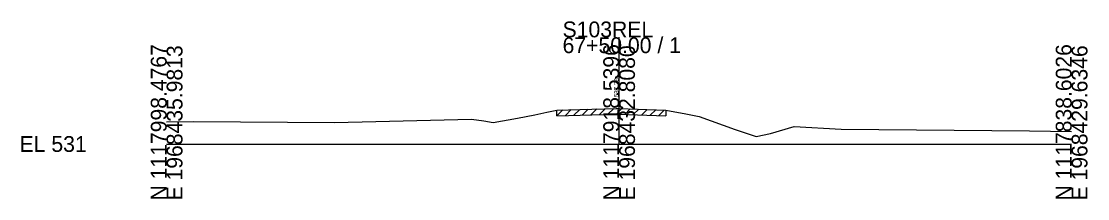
# Model space of a CAD drawing. Extents: x -26 to 163, y -10 to 24518.
# Drawn here: x -25.7 to 162.8, y 15990.3 to 16021.7 of the extents above; entities that cross this region are included whole.
import ezdxf

# ---------------------------------------------------------------- set-up
doc = ezdxf.new("R2010")
doc.units = 0
for name, color, linetype in [('RD_GPK_XS_Cell', 7, 'Continuous'), ('RD_XS_ExGround', 7, 'Continuous'), ('RD_XS_ExPaveRet', 7, 'Continuous'), ('RD_XS_TX_Elev_EX', 7, 'Continuous')]:
    doc.layers.add(name, color=color, linetype=linetype)

msp = doc.modelspace()

# ---------------------------------------------------------------- linework, layer by layer
at = {"layer": 'RD_GPK_XS_Cell'}
for p, q in [((80, 16000), (80, 16018.9)), ((0, 16000), (80, 16000)), ((80, 16000), (160, 16000))]:
    msp.add_line(p, q, dxfattribs=at)
at = {"layer": 'RD_XS_ExGround'}
msp.add_lwpolyline([(0, 16003.91), (4.73, 16003.97), (29.7, 16003.81), (37.01, 16003.98), (53.91, 16004.39), (56.1, 16004.09), (57.73, 16003.8), (62.05, 16004.58), (65.07, 16005.14), (67.24, 16005.65), (69.01, 16006.01), (75.15, 16006.19), (79.45, 16006.3), (80, 16006.28), (83.26, 16006.18), (88.24, 16006.02), (91.79, 16005.33), (94.17, 16004.89), (100.49, 16002.56), (104.2, 16001.32), (106.76, 16001.87), (110.97, 16003.08), (119.27, 16002.63), (152.57, 16002.35), (160, 16002.22)], dxfattribs=at)
at = {"layer": 'RD_XS_ExPaveRet'}
for p, q in [((69.01, 16005.01), (70.04, 16006.04)), ((69.01, 16005.01), (69.01, 16006.01)), ((69.01, 16005.01), (75.15, 16005.19)), ((70.51, 16005.06), (71.54, 16006.09)), ((72.01, 16005.1), (73.04, 16006.13)), ((73.51, 16005.14), (74.54, 16006.17)), ((75.01, 16005.18), (76.04, 16006.21)), ((75.15, 16005.19), (79.45, 16005.3)), ((76.51, 16005.22), (77.54, 16006.25)), ((78.01, 16005.26), (79.04, 16006.29)), ((79.45, 16005.3), (80, 16005.28)), ((79.51, 16005.3), (80.48, 16006.27)), ((80, 16005.28), (83.26, 16005.18)), ((81.01, 16005.25), (81.98, 16006.22)), ((82.51, 16005.2), (83.48, 16006.17)), ((83.26, 16005.18), (88.24, 16005.02)), ((84.01, 16005.15), (84.98, 16006.12)), ((85.51, 16005.1), (86.48, 16006.07)), ((87.01, 16005.06), (87.98, 16006.02)), ((88.24, 16006.02), (88.24, 16005.02))]:
    msp.add_line(p, q, dxfattribs=at)

# ---------------------------------------------------------------- texts
at = {"layer": 'RD_GPK_XS_Cell'}
for s, p in [('S103REL', (70, 16018.9)), ('67+50.00 / 1', (70, 16016.1)), ('EL 531', (-26, 15998.6))]:
    msp.add_text(s, height=2.8, dxfattribs=at).set_placement(p)
for s, p in [('N 1117998.4767', (0, 15990)), ('E 1968435.9813', (2.8, 15990)), ('N 1117918.5396', (80, 15990)), ('E 1968432.8080', (82.8, 15990)), ('N 1117838.6026', (160, 15990)), ('E 1968429.6346', (162.8, 15990))]:
    msp.add_text(s, height=2.8, rotation=90, dxfattribs=at).set_placement(p)
at = {"layer": 'RD_XS_TX_Elev_EX'}
msp.add_text('537.28', height=0.8, rotation=90, dxfattribs=at).set_placement((79.9, 16008.28))

doc.saveas('drawing.dxf')
